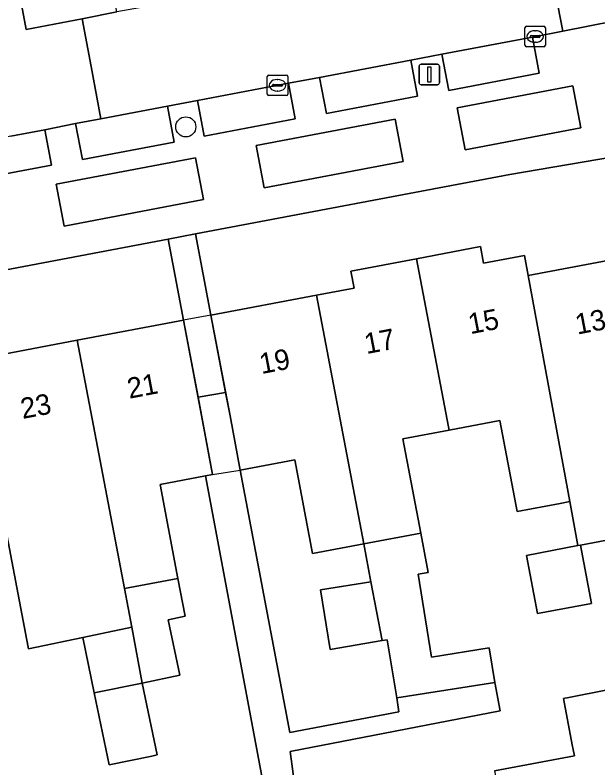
# Model space of a CAD drawing. Extents: x 158352 to 159489, y 383828 to 384603.
# Drawn here: x 158770.73 to 158799.12, y 384034.91 to 384071.58 of the extents above; entities that cross this region are included whole.
import ezdxf

# ---------------------------------------------------------------- set-up
doc = ezdxf.new("R2010")
doc.units = 0
for name, color, linetype in [('IMGEO_Boom', 7, 'Continuous'), ('IMGEO_Erf', 7, 'Continuous'), ('IMGEO_Groenvoorziening', 7, 'Continuous'), ('IMGEO_Kolk', 7, 'Continuous'), ('IMGEO_Lichtmast', 7, 'Continuous'), ('IMGEO_Pand', 7, 'Continuous'), ('IMGEO_Pand_nummerreeks', 7, 'Continuous'), ('IMGEO_Pand_overbouw', 7, 'Continuous'), ('IMGEO_Parkeervlak_open', 7, 'Continuous'), ('IMGEO_Rijbaan_lokaal_open', 7, 'Continuous'), ('IMGEO_Voetpad_open', 7, 'Continuous')]:
    doc.layers.add(name, color=color, linetype=linetype)

msp = doc.modelspace()

# ---------------------------------------------------------------- linework, layer by layer
at = {"layer": 'IMGEO_Boom'}
msp.add_circle((158779.049, 384066.133), 0.489, dxfattribs=at)
at = {"layer": 'IMGEO_Erf'}
for points in [[(158790.292, 384059.711), (158793.396, 384060.299), (158793.547, 384059.498), (158795.541, 384059.875), (158795.726, 384058.898), (158800.802, 384059.859), (158799.884, 384064.67), (158794.836, 384063.814), (158779.525, 384060.916), (158780.273, 384056.963), (158785.42, 384057.937), (158787.243, 384058.282), (158787.088, 384059.104)], [(158788.066, 384043.975), (158787.716, 384045.822), (158785.217, 384045.349), (158784.353, 384049.917), (158781.702, 384049.415), (158784.121, 384036.635), (158789.431, 384037.64), (158789.322, 384038.314), (158788.863, 384041.154), (158788.609, 384041.11), (158786.084, 384040.68), (158785.615, 384043.579)]]:
    msp.add_lwpolyline(points, close=True, dxfattribs=at)
for points in [[(158768.719, 384054.79), (158773.765, 384055.745), (158778.93, 384056.723), (158778.184, 384060.662), (158706.5, 384047.092)], [(158802.965, 384046.648), (158798.281, 384045.761), (158798.805, 384042.909), (158796.186, 384042.429), (158795.645, 384045.262), (158798.148, 384045.736), (158797.754, 384047.877), (158797.291, 384047.789), (158795.188, 384047.391), (158794.347, 384051.836), (158791.873, 384051.367), (158789.622, 384050.941), (158790.492, 384046.348), (158790.856, 384044.425), (158790.36, 384044.345), (158791.012, 384040.308), (158793.819, 384040.761), (158794.093, 384039.06), (158794.359, 384037.689), (158784.133, 384035.701), (158784.672, 384031.723)], [(158782.988, 384033.202), (158780.013, 384049.13), (158777.798, 384048.711), (158778.664, 384044.138), (158779.013, 384042.295), (158778.197, 384042.125), (158778.759, 384039.423), (158776.93, 384039.043), (158777.657, 384035.539), (158777.396, 384035.485), (158775.317, 384035.053), (158774.59, 384038.557), (158774.029, 384041.259), (158771.387, 384040.71), (158771.372, 384040.793), (158770.158, 384047.196)], [(158794.092, 384034.758), (158797.973, 384035.493), (158797.913, 384035.809), (158797.871, 384036.033), (158797.444, 384038.289), (158797.504, 384038.301), (158797.627, 384038.324), (158799.672, 384038.722)]]:
    msp.add_lwpolyline(points, dxfattribs=at)
at = {"layer": 'IMGEO_Groenvoorziening'}
for points in [[(158797.895, 384068.133), (158792.264, 384067.062), (158792.654, 384065.014), (158798.285, 384066.085)], [(158789.244, 384066.509), (158782.471, 384065.222), (158782.864, 384063.156), (158789.636, 384064.444)], [(158779.523, 384064.631), (158772.736, 384063.341), (158773.123, 384061.3), (158779.91, 384062.59)]]:
    msp.add_lwpolyline(points, close=True, dxfattribs=at)
at = {"layer": 'IMGEO_Kolk'}
for p, q in [((158795.564, 384070.109), (158795.564, 384070.961)), ((158795.639, 384071.035), (158796.491, 384071.035)), ((158796.052, 384070.815), (158796.077, 384070.815)), ((158796.565, 384070.961), (158796.565, 384070.109)), ((158795.823, 384070.529), (158795.823, 384070.541)), ((158796.261, 384070.492), (158795.863, 384070.492)), ((158795.866, 384070.578), (158796.264, 384070.578)), ((158796.307, 384070.541), (158796.307, 384070.529)), ((158796.491, 384070.035), (158795.639, 384070.035)), ((158796.075, 384070.255), (158796.05, 384070.255)), ((158783.015, 384067.732), (158783.015, 384068.584)), ((158783.09, 384068.658), (158783.942, 384068.658)), ((158784.016, 384068.584), (158784.016, 384067.732)), ((158783.317, 384068.201), (158783.715, 384068.201)), ((158783.503, 384068.438), (158783.528, 384068.438)), ((158783.274, 384068.152), (158783.274, 384068.164)), ((158783.712, 384068.115), (158783.314, 384068.115)), ((158783.526, 384067.878), (158783.501, 384067.878)), ((158783.758, 384068.164), (158783.758, 384068.152)), ((158783.942, 384067.658), (158783.09, 384067.658))]:
    msp.add_line(p, q, dxfattribs=at)
for points in [[(158795.564, 384070.109), (158795.564, 384070.961)], [(158795.639, 384071.035), (158796.491, 384071.035)], [(158796.565, 384070.961), (158796.565, 384070.109)], [(158796.491, 384070.035), (158795.639, 384070.035)], [(158783.015, 384067.732), (158783.015, 384068.584)], [(158783.09, 384068.658), (158783.942, 384068.658)], [(158784.016, 384068.584), (158784.016, 384067.732)], [(158783.942, 384067.658), (158783.09, 384067.658)]]:
    msp.add_lwpolyline(points, dxfattribs=at)
for centre, radius, start, end in [((158795.641, 384070.959), 0.0765, 91.552, 178.448), ((158795.641, 384070.959), 0.0765, 91.552, 178.448), ((158796.489, 384070.959), 0.0765, 1.552, 88.448), ((158796.489, 384070.959), 0.0765, 1.552, 88.448), ((158795.863, 384070.538), 0.0403, 85.8775, 175.7526), ((158795.86, 384070.528), 0.0366, 178.938, 274.7102), ((158796.264, 384070.535), 0.043, 264.8664, 352.4533), ((158796.268, 384070.54), 0.0386, 1.7309, 96.639), ((158795.641, 384070.111), 0.0765, 181.552, 268.448), ((158795.641, 384070.111), 0.0765, 181.552, 268.448), ((158796.489, 384070.111), 0.0765, 271.552, 358.448), ((158796.489, 384070.111), 0.0765, 271.552, 358.448), ((158783.092, 384068.582), 0.0765, 91.552, 178.448), ((158783.092, 384068.582), 0.0765, 91.552, 178.448), ((158783.94, 384068.582), 0.0765, 1.552, 88.448), ((158783.94, 384068.582), 0.0765, 1.552, 88.448), ((158783.314, 384068.161), 0.0403, 85.8775, 175.7526), ((158783.719, 384068.163), 0.0386, 1.7309, 96.639), ((158783.311, 384068.151), 0.0366, 178.938, 274.7102), ((158783.715, 384068.158), 0.043, 264.8664, 352.4533), ((158783.092, 384067.734), 0.0765, 181.552, 268.448), ((158783.092, 384067.734), 0.0765, 181.552, 268.448), ((158783.94, 384067.734), 0.0765, 271.552, 358.448), ((158783.94, 384067.734), 0.0765, 271.552, 358.448)]:
    msp.add_arc(centre, radius, start, end, dxfattribs=at)
for centre, major_axis, ratio, start_param, end_param in [((158796.051, 384070.535), (-0.387, 0.002), 0.722429, 4.712389, 7.853982), ((158796.076, 384070.535), (-0.39, 0.002), 0.717154, 1.570796, 4.712389), ((158783.502, 384068.158), (-0.387, 0.002), 0.722429, 4.712389, 7.853982), ((158783.527, 384068.158), (-0.39, 0.002), 0.717154, 1.570796, 4.712389)]:
    msp.add_ellipse(centre, major_axis=major_axis, ratio=ratio, start_param=start_param, end_param=end_param, dxfattribs=at)
at = {"layer": 'IMGEO_Lichtmast'}
for p, q in [((158790.414, 384068.284), (158790.414, 384069.084)), ((158790.414, 384069.084), (158790.414, 384068.284)), ((158790.514, 384069.184), (158791.304, 384069.184)), ((158791.304, 384069.184), (158790.514, 384069.184)), ((158791.404, 384069.084), (158791.404, 384068.284)), ((158791.404, 384068.284), (158791.404, 384069.084)), ((158791.304, 384068.184), (158790.514, 384068.184)), ((158790.514, 384068.184), (158791.304, 384068.184))]:
    msp.add_line(p, q, dxfattribs=at)
msp.add_lwpolyline([(158790.834, 384069.059), (158790.984, 384069.059), (158790.984, 384068.309), (158790.834, 384068.309), (158790.834, 384069.059)], dxfattribs=at)
for centre, start, end in [((158790.514, 384069.084), 90, 180), ((158790.514, 384069.084), 90, 180), ((158791.304, 384069.084), 0, 90), ((158791.304, 384069.084), 360, 90), ((158790.514, 384068.284), 180, 270), ((158790.514, 384068.284), 180, 270), ((158791.304, 384068.284), 270, 0), ((158791.304, 384068.284), 270, 0)]:
    msp.add_arc(centre, 0.1, start, end, dxfattribs=at)
at = {"layer": 'IMGEO_Pand'}
for points in [[(158795.726, 384058.898), (158795.541, 384059.875), (158793.547, 384059.498), (158793.396, 384060.299), (158790.292, 384059.711), (158791.842, 384051.529), (158791.873, 384051.367), (158794.347, 384051.836), (158795.188, 384047.391), (158797.291, 384047.789), (158797.754, 384047.877)], [(158801.638, 384053.658), (158801.964, 384053.719), (158800.802, 384059.859), (158795.726, 384058.898), (158797.754, 384047.877), (158798.148, 384045.736), (158798.281, 384045.761), (158802.965, 384046.648)], [(158785.42, 384057.937), (158787.716, 384045.822), (158790.492, 384046.348), (158789.622, 384050.941), (158791.873, 384051.367), (158791.842, 384051.529), (158790.292, 384059.711), (158787.088, 384059.104), (158787.243, 384058.282)], [(158785.42, 384057.937), (158780.273, 384056.963), (158781.203, 384052.051), (158781.702, 384049.415), (158784.353, 384049.917), (158785.217, 384045.349), (158787.716, 384045.822)], [(158779.86, 384051.811), (158778.93, 384056.723), (158773.765, 384055.745), (158776.058, 384043.644), (158778.664, 384044.138), (158777.798, 384048.711), (158780.013, 384049.13), (158780.355, 384049.195)], [(158773.765, 384055.745), (158768.719, 384054.79), (158770.089, 384047.561), (158770.158, 384047.196), (158771.372, 384040.793), (158771.387, 384040.71), (158774.029, 384041.259), (158776.416, 384041.755), (158776.058, 384043.644)], [(158790.36, 384044.345), (158790.856, 384044.425), (158790.492, 384046.348), (158787.716, 384045.822), (158788.066, 384043.975), (158788.609, 384041.11), (158788.863, 384041.154), (158789.322, 384038.314), (158794.093, 384039.06), (158793.819, 384040.761), (158791.012, 384040.308)], [(158798.281, 384045.761), (158798.148, 384045.736), (158795.645, 384045.262), (158796.186, 384042.429), (158798.805, 384042.909)], [(158778.197, 384042.125), (158779.013, 384042.295), (158778.664, 384044.138), (158776.058, 384043.644), (158776.416, 384041.755), (158776.93, 384039.043), (158778.759, 384039.423)], [(158788.609, 384041.11), (158788.066, 384043.975), (158785.615, 384043.579), (158786.084, 384040.68)], [(158776.416, 384041.755), (158774.029, 384041.259), (158774.59, 384038.557), (158776.93, 384039.043)], [(158804.584, 384039.651), (158799.672, 384038.722), (158797.627, 384038.324), (158797.504, 384038.301), (158797.444, 384038.289), (158797.871, 384036.033), (158797.913, 384035.809), (158797.973, 384035.493), (158794.092, 384034.758), (158794.532, 384032.433), (158794.797, 384032.483), (158805.555, 384034.519)], [(158776.93, 384039.043), (158774.59, 384038.557), (158775.317, 384035.053), (158777.396, 384035.485), (158777.657, 384035.539)]]:
    msp.add_lwpolyline(points, close=True, dxfattribs=at)
at = {"layer": 'IMGEO_Pand_overbouw'}
for points in [[(158778.93, 384056.723), (158779.643, 384052.959), (158780.988, 384053.189), (158780.273, 384056.963)], [(158780.988, 384053.189), (158779.643, 384052.959), (158780.355, 384049.195), (158781.702, 384049.415), (158781.203, 384052.051)]]:
    msp.add_lwpolyline(points, close=True, dxfattribs=at)
at = {"layer": 'IMGEO_Parkeervlak_open'}
for points in [[(158775.689, 384071.732), (158775.359, 384073.468), (158770.945, 384072.629), (158771.279, 384070.877), (158774.001, 384071.394)], [(158791.518, 384069.674), (158791.853, 384067.908), (158796.267, 384068.747), (158795.932, 384070.51)], [(158785.56, 384068.545), (158785.895, 384066.784), (158790.342, 384067.629), (158790.008, 384069.388)], [(158784.05, 384068.259), (158779.617, 384067.419), (158779.949, 384065.678), (158784.381, 384066.52)], [(158774.903, 384066.526), (158773.679, 384066.293), (158774.013, 384064.536), (158778.483, 384065.386), (158778.151, 384067.134)], [(158767.685, 384065.138), (158768.007, 384063.423), (158772.512, 384064.267), (158772.19, 384065.987), (158770.519, 384065.673)]]:
    msp.add_lwpolyline(points, close=True, dxfattribs=at)
at = {"layer": 'IMGEO_Rijbaan_lokaal_open'}
msp.add_lwpolyline([(158774.903, 384066.526), (158778.151, 384067.134), (158779.617, 384067.419), (158784.05, 384068.259), (158785.56, 384068.545), (158790.008, 384069.388), (158791.518, 384069.674), (158795.932, 384070.51), (158797.406, 384070.789), (158796.941, 384073.236), (158796.479, 384075.67), (158794.108, 384075.252), (158792.642, 384074.941), (158788.201, 384074.097), (158786.738, 384073.819), (158782.161, 384072.948), (158781.621, 384072.846), (158777.077, 384071.982), (158775.689, 384071.732), (158774.001, 384071.394), (158774.431, 384069.073)], close=True, dxfattribs=at)
at = {"layer": 'IMGEO_Voetpad_open'}
for points in [[(158796.941, 384073.236), (158797.406, 384070.789), (158801.193, 384071.537)], [(158770.519, 384065.673), (158772.19, 384065.987), (158773.679, 384066.293), (158774.903, 384066.526), (158774.431, 384069.073), (158774.001, 384071.394), (158771.279, 384070.877), (158770.945, 384072.629)], [(158801.193, 384071.537), (158797.406, 384070.789), (158795.932, 384070.51), (158796.267, 384068.747), (158791.853, 384067.908), (158791.518, 384069.674), (158790.008, 384069.388), (158790.342, 384067.629), (158785.895, 384066.784), (158785.56, 384068.545), (158784.05, 384068.259), (158784.381, 384066.52), (158779.949, 384065.678), (158779.617, 384067.419), (158778.151, 384067.134), (158778.483, 384065.386), (158774.013, 384064.536), (158773.679, 384066.293), (158772.19, 384065.987), (158772.512, 384064.267), (158768.007, 384063.423)], [(158698.177, 384045.516), (158706.5, 384047.092), (158778.184, 384060.662), (158779.525, 384060.916), (158794.836, 384063.814), (158799.884, 384064.67), (158803.354, 384065.259)], [(158784.672, 384031.723), (158784.133, 384035.701), (158794.359, 384037.689), (158794.093, 384039.06), (158789.322, 384038.314), (158789.431, 384037.64), (158784.121, 384036.635), (158781.702, 384049.415), (158781.203, 384052.051), (158780.273, 384056.963), (158779.525, 384060.916), (158778.184, 384060.662), (158778.93, 384056.723), (158779.86, 384051.811), (158780.355, 384049.195), (158780.013, 384049.13), (158782.988, 384033.202)]]:
    msp.add_lwpolyline(points, dxfattribs=at)
for points in [[(158792.264, 384067.062), (158797.895, 384068.133), (158798.285, 384066.085), (158792.654, 384065.014)], [(158789.636, 384064.444), (158782.864, 384063.156), (158782.471, 384065.222), (158789.244, 384066.509)], [(158779.91, 384062.59), (158773.123, 384061.3), (158772.736, 384063.341), (158779.523, 384064.631)]]:
    msp.add_lwpolyline(points, close=True, dxfattribs=at)

# ---------------------------------------------------------------- texts
at = {"layer": 'IMGEO_Pand_nummerreeks'}
for s, rotation, p in [('15', 10.8461, (158792.906, 384056.031)), ('13', 10.72, (158798.117, 384056.013)), ('17', 10.8454, (158787.846, 384055.062)), ('19', 10.705, (158782.733, 384054.09)), ('21', 10.72, (158776.296, 384052.887)), ('23', 10.72, (158771.099, 384051.903))]:
    msp.add_text(s, height=1, rotation=rotation, dxfattribs=at).set_placement(p)

doc.saveas('drawing.dxf')
